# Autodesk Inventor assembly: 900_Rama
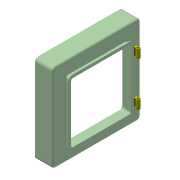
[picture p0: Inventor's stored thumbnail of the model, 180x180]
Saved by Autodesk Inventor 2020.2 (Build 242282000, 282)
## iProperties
Created: 2006-01
Part Number: 900_Rama
Document SubType Name: Konstrukcja spawana
Designer: F.Stasiak
Stock Number: Rama
Weld Material: Spawana stal miękka
Manager: www.cadconsulting.pl
Company: Fabian Stasiak CAD Consulting
Author: F.Stasiak
Subject: Zbiór ćwiczeń. Autodesk Inventor 2020. Kurs podstawowy
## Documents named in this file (3)
- C:\2020_Kurs_podstawowy\R7 Prezentacje\Komponenty\900_Rama.iam
- C:\2020_Kurs_podstawowy\R7 Prezentacje\Komponenty\900_Blacha1.ipt
- C:\2020_Kurs_podstawowy\R7 Prezentacje\Komponenty\900_Zawias1.ipt
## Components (3 placed, 2 different names)
1. 900_Blacha1:1 — Równoległy:1, Równoległy:2, Równoległy:3
2. 900_Zawias1:1 — Równoległy:1, Równoległy:2, Równoległy:3, Zestawiający:1, Równoległy:4, Równoległy:5
3. 900_Zawias1:2 — Zestawiający:1, Równoległy:4, Równoległy:5
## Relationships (6: Flush 5, Mate 1)
- Równoległy:1 [Flush]: 900_Blacha1:1 ↔ 900_Zawias1:1
- Równoległy:2 [Flush]: 900_Blacha1:1 ↔ 900_Zawias1:1
- Równoległy:3 [Flush]: 900_Blacha1:1 ↔ 900_Zawias1:1
- Zestawiający:1 [Mate]: 900_Zawias1:1 ↔ 900_Zawias1:2
- Równoległy:4 [Flush]: 900_Zawias1:1 ↔ 900_Zawias1:2
- Równoległy:5 [Flush]: 900_Zawias1:1 ↔ 900_Zawias1:2
